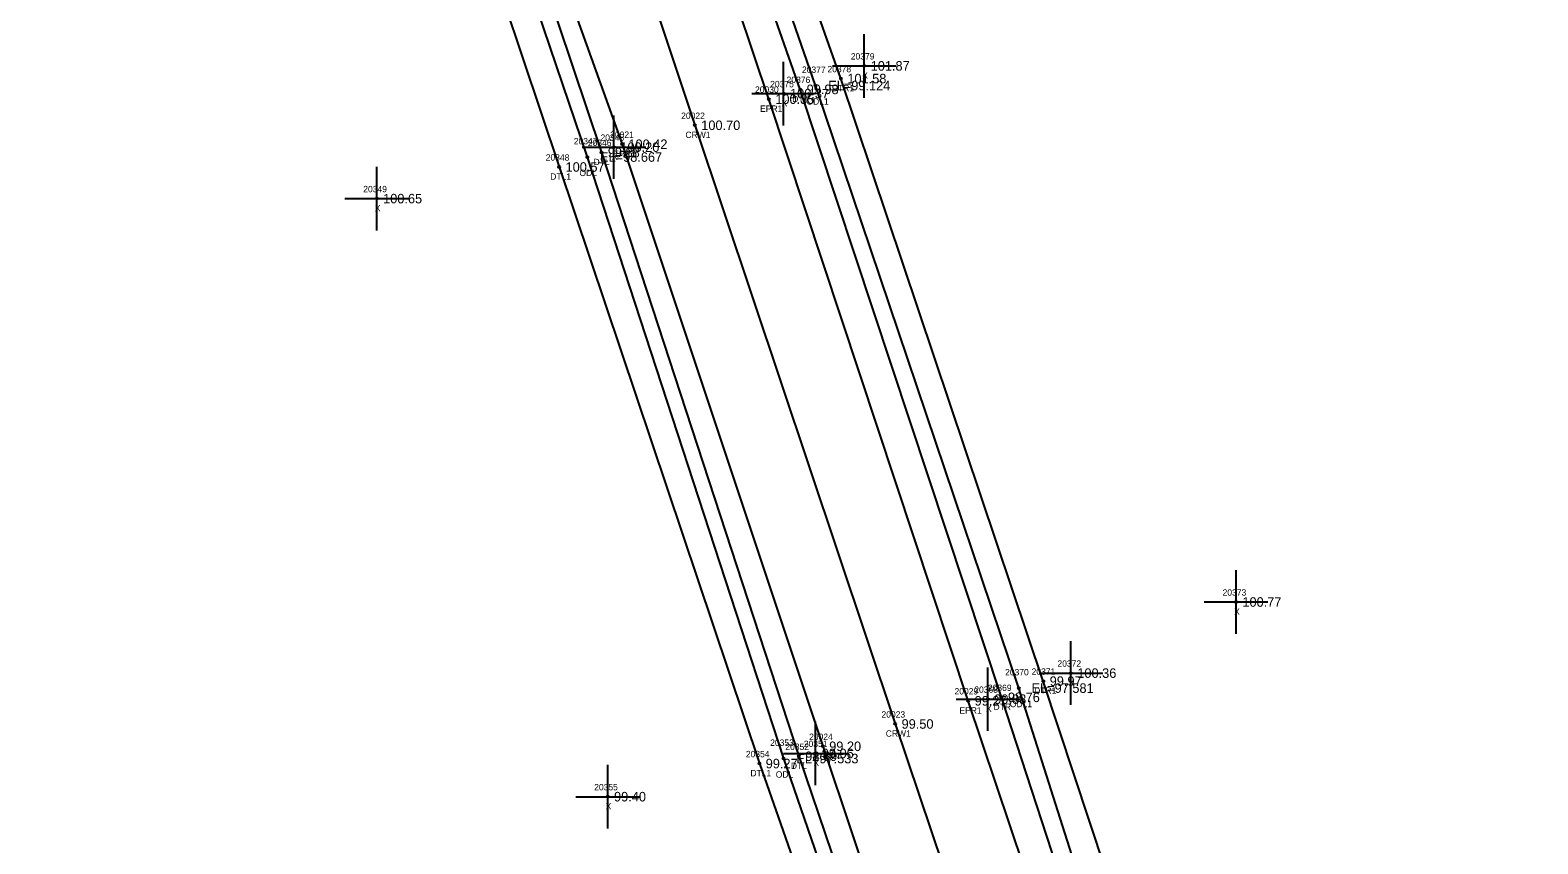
# Model space of a CAD drawing. Extents: x 2530197 to 2532051, y 935230 to 936631.
# Drawn here: x 2530401.9 to 2530638.9, y 935343.8 to 935471.7 of the extents above; entities that cross this region are included whole.
import ezdxf

# ---------------------------------------------------------------- set-up
doc = ezdxf.new("R2010")
doc.units = 0
for name, color, linetype in [('RD_DTM_BkLn1', 7, 'Continuous'), ('RD_EX_H2O', 7, 'Continuous'), ('RD_EX_H2O_txCode', 7, 'Continuous'), ('RD_EX_Misc', 7, 'Continuous'), ('RD_EX_Misc_txCode', 7, 'Continuous'), ('RD_EX_Road', 7, 'Continuous'), ('RD_EX_Road_txCode', 7, 'Continuous'), ('RD_EX_TX_H2O_ELEV', 7, 'Continuous'), ('RD_EX_TX_Misc_ELEV', 7, 'Continuous'), ('RD_EX_TX_Road_ELEV', 7, 'Continuous'), ('RD_HC_Survey_ELEV', 7, 'Continuous'), ('RD_HC_Survey_txCode', 7, 'Continuous'), ('RD_SMD_Locator', 7, 'Continuous')]:
    doc.layers.add(name, color=color, linetype=linetype)

msp = doc.modelspace()

# ---------------------------------------------------------------- linework, layer by layer
at = {"layer": 'RD_DTM_BkLn1'}
msp.add_lwpolyline([(2530465.37, 935579.66), (2530474.48, 935552.87), (2530506.43, 935456.79), (2530537.92, 935362.65), (2530570.08, 935267.03)], dxfattribs=at)
at = {"layer": 'RD_EX_H2O'}
for points in [[(2530585.61, 935271.89), (2530554.63, 935366.84), (2530523, 935462.44), (2530497.71, 935534.53), (2530497.63, 935550.35), (2530501.9, 935567.07), (2530512.76, 935580.06), (2530532.29, 935593.54), (2530580.75, 935621.41), (2530622.78, 935645.99), (2530706.38, 935694.8)], [(2530592.81, 935273.73), (2530561.2, 935369.39), (2530529.39, 935464.13), (2530504.24, 935535.46), (2530502.94, 935549.83), (2530506.75, 935563.82), (2530516.63, 935575.2), (2530535.16, 935588.8), (2530583.24, 935617.5), (2530624.86, 935641.7), (2530708.31, 935690.59), (2530708.33, 935693.17), (2530706.38, 935694.8)], [(2530587.86, 935272.38), (2530557.35, 935368.29), (2530525.38, 935463.03), (2530500.38, 935535.14), (2530499.61, 935550.4), (2530504.44, 935565.67), (2530514.36, 935577.87), (2530533.45, 935591.79), (2530582.01, 935619.78), (2530623.26, 935643.67), (2530705.7, 935692.18)], [(2530212.43, 935575.3), (2530312.61, 935575.57), (2530413.4, 935574.03), (2530431.14, 935570.94), (2530447.74, 935563.43), (2530459.72, 935547.88), (2530491.74, 935452.52), (2530522.77, 935357.57), (2530554.82, 935263)], [(2530212.28, 935572.05), (2530311.96, 935572.07), (2530413.48, 935570.72), (2530429.97, 935567.74), (2530445.97, 935560.86), (2530457.18, 935547.13), (2530489.52, 935451.8), (2530520.38, 935357.21), (2530552.97, 935262.56)], [(2530212.78, 935569.06), (2530311.54, 935568.98), (2530412.57, 935565.49), (2530428.32, 935562.93), (2530442.59, 935555.84), (2530453.4, 935544.85), (2530485.1, 935450.23), (2530516.56, 935356.42), (2530549.63, 935261.88)]]:
    msp.add_lwpolyline(points, dxfattribs=at)
at = {"layer": 'RD_EX_Misc'}
for p, q in [((2530533.06, 935461.13), (2530533.06, 935471.13)), ((2530520.38, 935456.77), (2530520.38, 935466.77)), ((2530528.06, 935466.13), (2530538.06, 935466.13)), ((2530515.38, 935461.77), (2530525.38, 935461.77)), ((2530493.71, 935448.35), (2530493.71, 935458.35)), ((2530488.71, 935453.35), (2530498.71, 935453.35)), ((2530456.42, 935440.26), (2530456.42, 935450.26)), ((2530451.42, 935445.26), (2530461.42, 935445.26)), ((2530591.49, 935376.83), (2530591.49, 935386.83)), ((2530586.49, 935381.83), (2530596.49, 935381.83)), ((2530565.54, 935365.65), (2530565.54, 935375.65)), ((2530552.49, 935361.55), (2530552.49, 935371.55)), ((2530560.54, 935370.65), (2530570.54, 935370.65)), ((2530547.49, 935366.55), (2530557.49, 935366.55)), ((2530525.38, 935353.02), (2530525.38, 935363.02)), ((2530520.38, 935358.02), (2530530.38, 935358.02)), ((2530492.72, 935346.22), (2530492.72, 935356.22)), ((2530487.72, 935351.22), (2530497.72, 935351.22))]:
    msp.add_line(p, q, dxfattribs=at)
at = {"layer": 'RD_EX_Road'}
for points in [[(2530591.21, 935242.46), (2530571.43, 935300.61), (2530549.4, 935366.29), (2530518.07, 935460.9), (2530493.7, 935533.55), (2530494.46, 935557.42), (2530501.12, 935573.63), (2530518.05, 935590.5), (2530533.43, 935598.45)], [(2530402.98, 935580.64), (2530413.62, 935578.66), (2530430.98, 935574.56), (2530444.41, 935568.86), (2530451.97, 935562.31), (2530461.09, 935548.32), (2530494.98, 935453.81), (2530526.54, 935359.14), (2530558.58, 935263.43)]]:
    msp.add_lwpolyline(points, dxfattribs=at)
at = {"layer": 'RD_SMD_Locator'}
for centre in [(2530533.06, 935466.13), (2530523, 935462.44), (2530525.38, 935463.03), (2530529.39, 935464.13), (2530518.07, 935460.9), (2530520.38, 935461.77), (2530506.43, 935456.79), (2530493.71, 935453.35), (2530494.98, 935453.81), (2530485.1, 935450.23), (2530489.52, 935451.8), (2530491.74, 935452.52), (2530456.42, 935445.26), (2530591.49, 935381.83), (2530565.54, 935370.65), (2530557.35, 935368.29), (2530561.2, 935369.39), (2530549.4, 935366.29), (2530552.49, 935366.55), (2530554.63, 935366.84), (2530537.92, 935362.65), (2530525.38, 935358.02), (2530526.54, 935359.14), (2530516.56, 935356.42), (2530520.38, 935357.21), (2530522.77, 935357.57), (2530492.72, 935351.22)]:
    msp.add_circle(centre, 0.15, dxfattribs=at)

# ---------------------------------------------------------------- texts
at = {"layer": 'RD_EX_H2O_txCode'}
for s, p in [('20377', (2530523.26, 935465.03)), ('20378', (2530527.27, 935465.13)), ('20376', (2530520.85, 935463.44)), ('DTR1', (2530527.96, 935462.13)), ('DTR', (2530521.73, 935460.44)), ('ODL1', (2530523.97, 935460.03)), ('20347', (2530487.4, 935453.8)), ('20346', (2530489.6, 935453.52)), ('20348', (2530482.98, 935451.23)), ('DTL', (2530490.5, 935450.52)), ('DTL1', (2530483.69, 935448.23)), ('ODL', (2530488.28, 935448.8)), ('20370', (2530555.19, 935370.29)), ('20371', (2530559.36, 935370.39)), ('20369', (2530552.49, 935367.84)), ('DTR1', (2530559.76, 935367.39)), ('DTR', (2530553.37, 935364.84)), ('ODL1', (2530555.94, 935365.29)), ('20354', (2530514.44, 935357.42)), ('20353', (2530518.26, 935359.21)), ('20352', (2530520.65, 935358.57)), ('DTL', (2530521.52, 935355.57)), ('DTL1', (2530515.15, 935354.42)), ('ODL', (2530519.14, 935354.21))]:
    msp.add_text(s, height=1, dxfattribs=at).set_placement(p)
at = {"layer": 'RD_EX_Misc_txCode'}
for s, p in [('20379', (2530530.94, 935467.13)), ('X', (2530532.75, 935464.13)), ('20375', (2530518.26, 935462.77)), ('X', (2530520.06, 935459.77)), ('20345', (2530491.59, 935454.35)), ('X', (2530493.39, 935451.35)), ('20349', (2530454.3, 935446.26)), ('X', (2530456.11, 935443.26)), ('20373', (2530589.38, 935382.83)), ('X', (2530591.18, 935379.83)), ('20372', (2530563.42, 935371.65)), ('20368', (2530550.35, 935367.55)), ('X', (2530565.22, 935368.65)), ('X', (2530552.18, 935364.55)), ('20351', (2530523.55, 935359.02)), ('X', (2530525.07, 935356.02)), ('20355', (2530490.6, 935352.22)), ('X', (2530492.4, 935349.22))]:
    msp.add_text(s, height=1, dxfattribs=at).set_placement(p)
at = {"layer": 'RD_EX_Road_txCode'}
for s, p in [('20030', (2530515.88, 935461.9)), ('EPR1', (2530516.68, 935458.9)), ('20021', (2530493.11, 935454.81)), ('EPR1', (2530493.59, 935451.81)), ('20029', (2530547.24, 935367.29)), ('EPR1', (2530548.01, 935364.29)), ('20024', (2530524.38, 935360.14)), ('EPR1', (2530525.14, 935357.14))]:
    msp.add_text(s, height=1, dxfattribs=at).set_placement(p)
at = {"layer": 'RD_EX_TX_H2O_ELEV'}
for s, p in [('101.58', (2530530.39, 935463.38)), ('99.98', (2530524, 935461.69)), ('EL=99.124', (2530527.38, 935462.28)), ('99.88', (2530492.74, 935451.77)), ('100.57', (2530486.1, 935449.48)), ('EL=98.667', (2530491.52, 935451.05)), ('99.97', (2530562.2, 935368.64)), ('98.76', (2530555.63, 935366.09)), ('EL=97.581', (2530559.35, 935367.54)), ('EL=97.533', (2530522.38, 935356.46)), ('98.69', (2530523.77, 935356.82)), ('99.27', (2530517.56, 935355.67))]:
    msp.add_text(s, height=1.5, dxfattribs=at).set_placement(p)
at = {"layer": 'RD_EX_TX_Misc_ELEV'}
for s, p in [('101.87', (2530534.06, 935465.38)), ('100.37', (2530521.38, 935461.02)), ('100.20', (2530494.71, 935452.6)), ('100.65', (2530457.42, 935444.51)), ('100.77', (2530592.49, 935381.08)), ('100.36', (2530566.54, 935369.9)), ('99.08', (2530553.49, 935365.8)), ('99.06', (2530526.38, 935357.27)), ('99.40', (2530493.72, 935350.47))]:
    msp.add_text(s, height=1.5, dxfattribs=at).set_placement(p)
at = {"layer": 'RD_EX_TX_Road_ELEV'}
for s, p in [('100.35', (2530519.07, 935460.15)), ('100.42', (2530495.98, 935453.06)), ('99.27', (2530550.4, 935365.54)), ('99.20', (2530527.54, 935358.39))]:
    msp.add_text(s, height=1.5, dxfattribs=at).set_placement(p)
at = {"layer": 'RD_HC_Survey_ELEV'}
for s, p in [('100.70', (2530507.43, 935456.04)), ('99.50', (2530538.92, 935361.9))]:
    msp.add_text(s, height=1.5, dxfattribs=at).set_placement(p)
at = {"layer": 'RD_HC_Survey_txCode'}
for s, p in [('20022', (2530504.27, 935457.79)), ('CRW1', (2530504.95, 935454.79)), ('20023', (2530535.76, 935363.65)), ('CRW1', (2530536.43, 935360.65))]:
    msp.add_text(s, height=1, dxfattribs=at).set_placement(p)

doc.saveas('drawing.dxf')
